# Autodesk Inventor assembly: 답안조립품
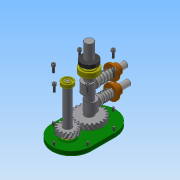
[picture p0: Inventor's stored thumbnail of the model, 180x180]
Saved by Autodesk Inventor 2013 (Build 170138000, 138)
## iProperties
Created: 2018-10
Part Number: 답안조립품
Document SubType Name: Assembly
Designer: Administrator
Author: Administrator
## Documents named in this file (15)
- C:\Users\Administrator\Desktop\381007V1014\답안조립품.iam
- C:\Users\Administrator\Desktop\381007V1014\본체.ipt
- C:\Users\Administrator\Desktop\381007V1014\뒤커버.ipt
- C:\Users\Administrator\Desktop\381007V1014\메인축.ipt
- C:\Users\Administrator\Desktop\381007V1014\베어링 608.ipt
- C:\Users\Administrator\Desktop\381007V1014\베어링 6003.ipt
- C:\Users\Administrator\Desktop\381007V1014\볼트 M4.ipt
- C:\Users\Administrator\Desktop\381007V1014\부시.ipt
- C:\Users\Administrator\Desktop\381007V1014\서브축.ipt
- C:\Users\Administrator\Desktop\381007V1014\슬라이더.ipt
- C:\Users\Administrator\Desktop\381007V1014\앞커버.ipt
- C:\Users\Administrator\Desktop\381007V1014\오일실 8 22 7.ipt
- C:\Users\Administrator\Desktop\381007V1014\오일실 17 32 8.ipt
- C:\Users\Administrator\Desktop\381007V1014\가변스프링1.ipt
- C:\Users\Administrator\Desktop\381007V1014\가변스프링2.ipt
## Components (2 placed, 2 different names)
1. 가변스프링1:1
2. 가변스프링2:1
